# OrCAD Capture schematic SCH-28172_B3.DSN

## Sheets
1 TABLE OF CONTENT/REVISIONS: title: FRDM-KL03Z; rev: B3; company: Freescale Semiconductor; note: SCH-28172 PDF:SPF-28172; note: 6501 William Cannon Drive West; note: Austin, TX 78735-8598
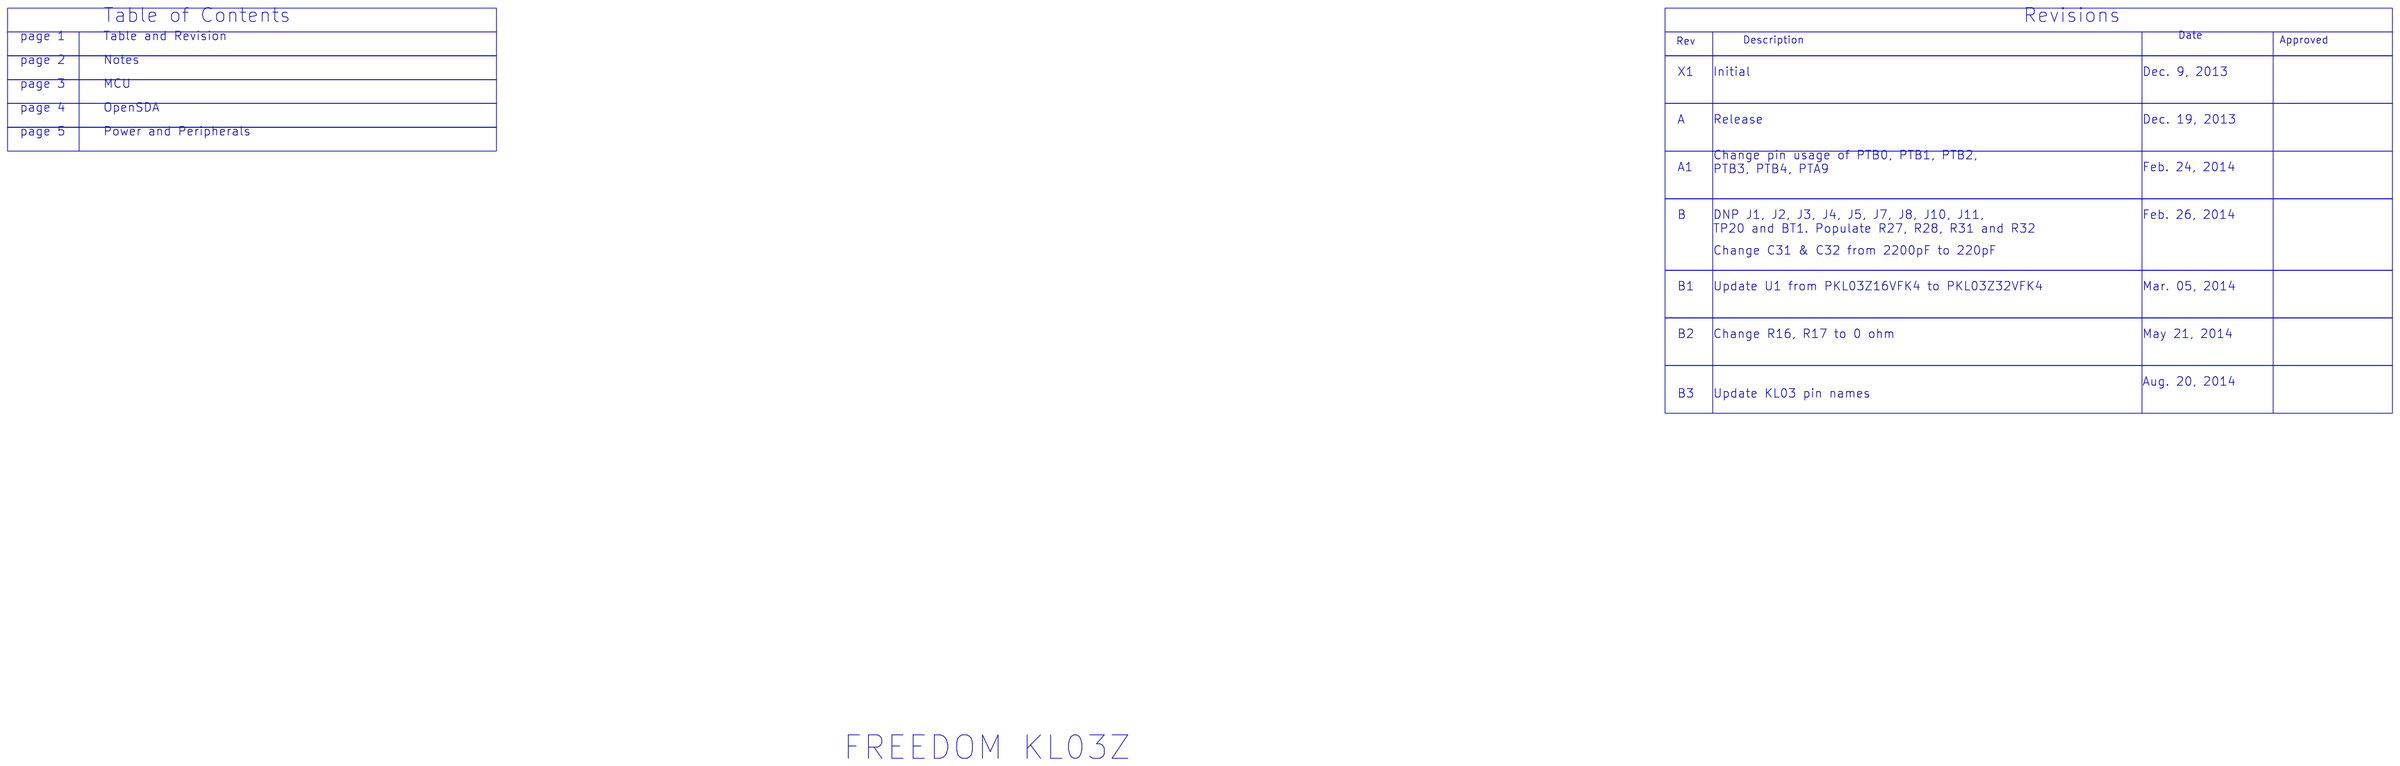
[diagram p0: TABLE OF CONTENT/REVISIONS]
2 NOTES
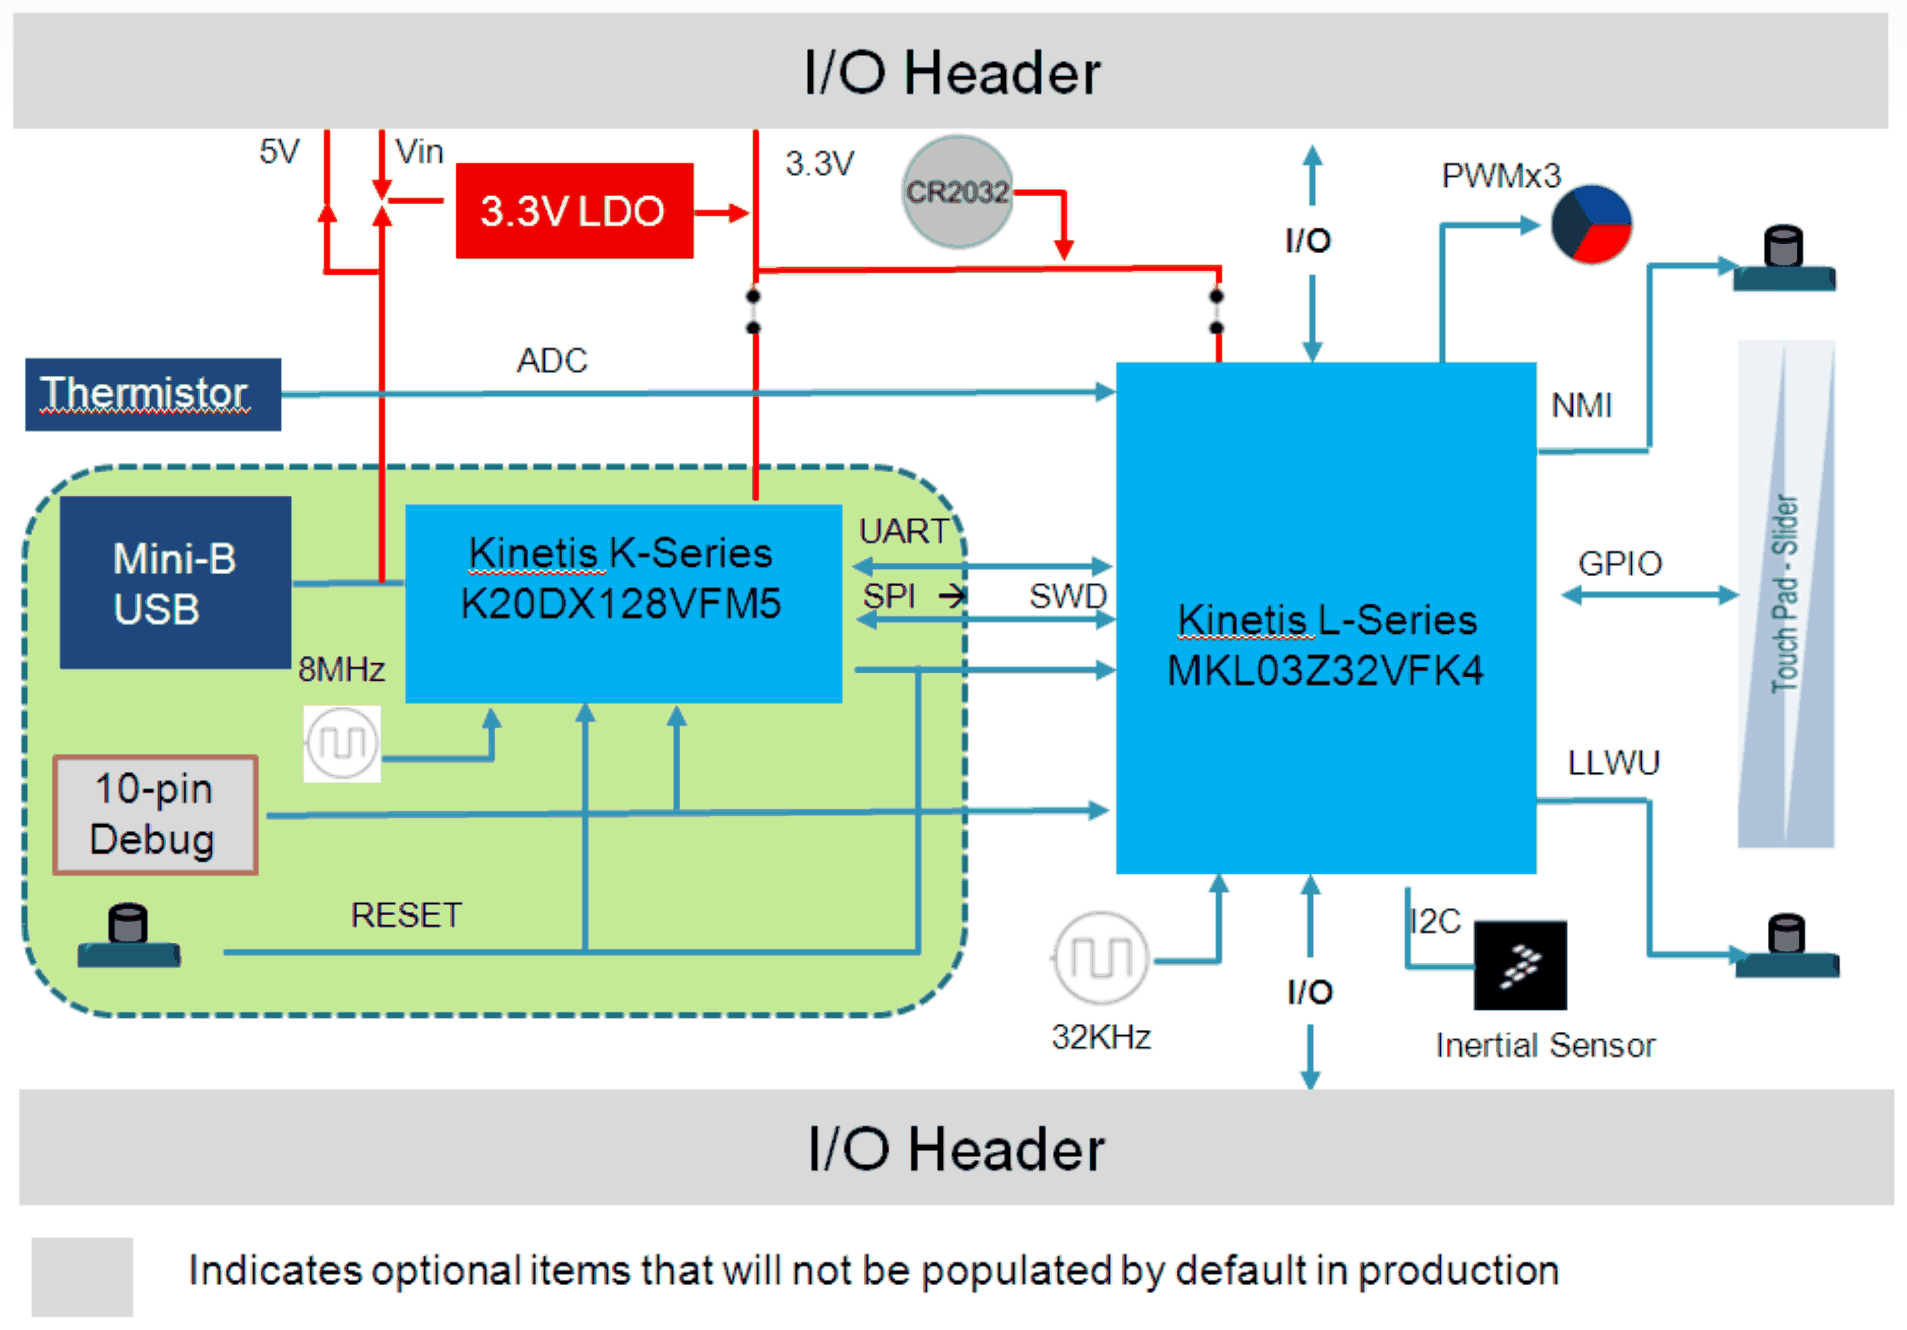
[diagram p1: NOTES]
3 MCU: size C
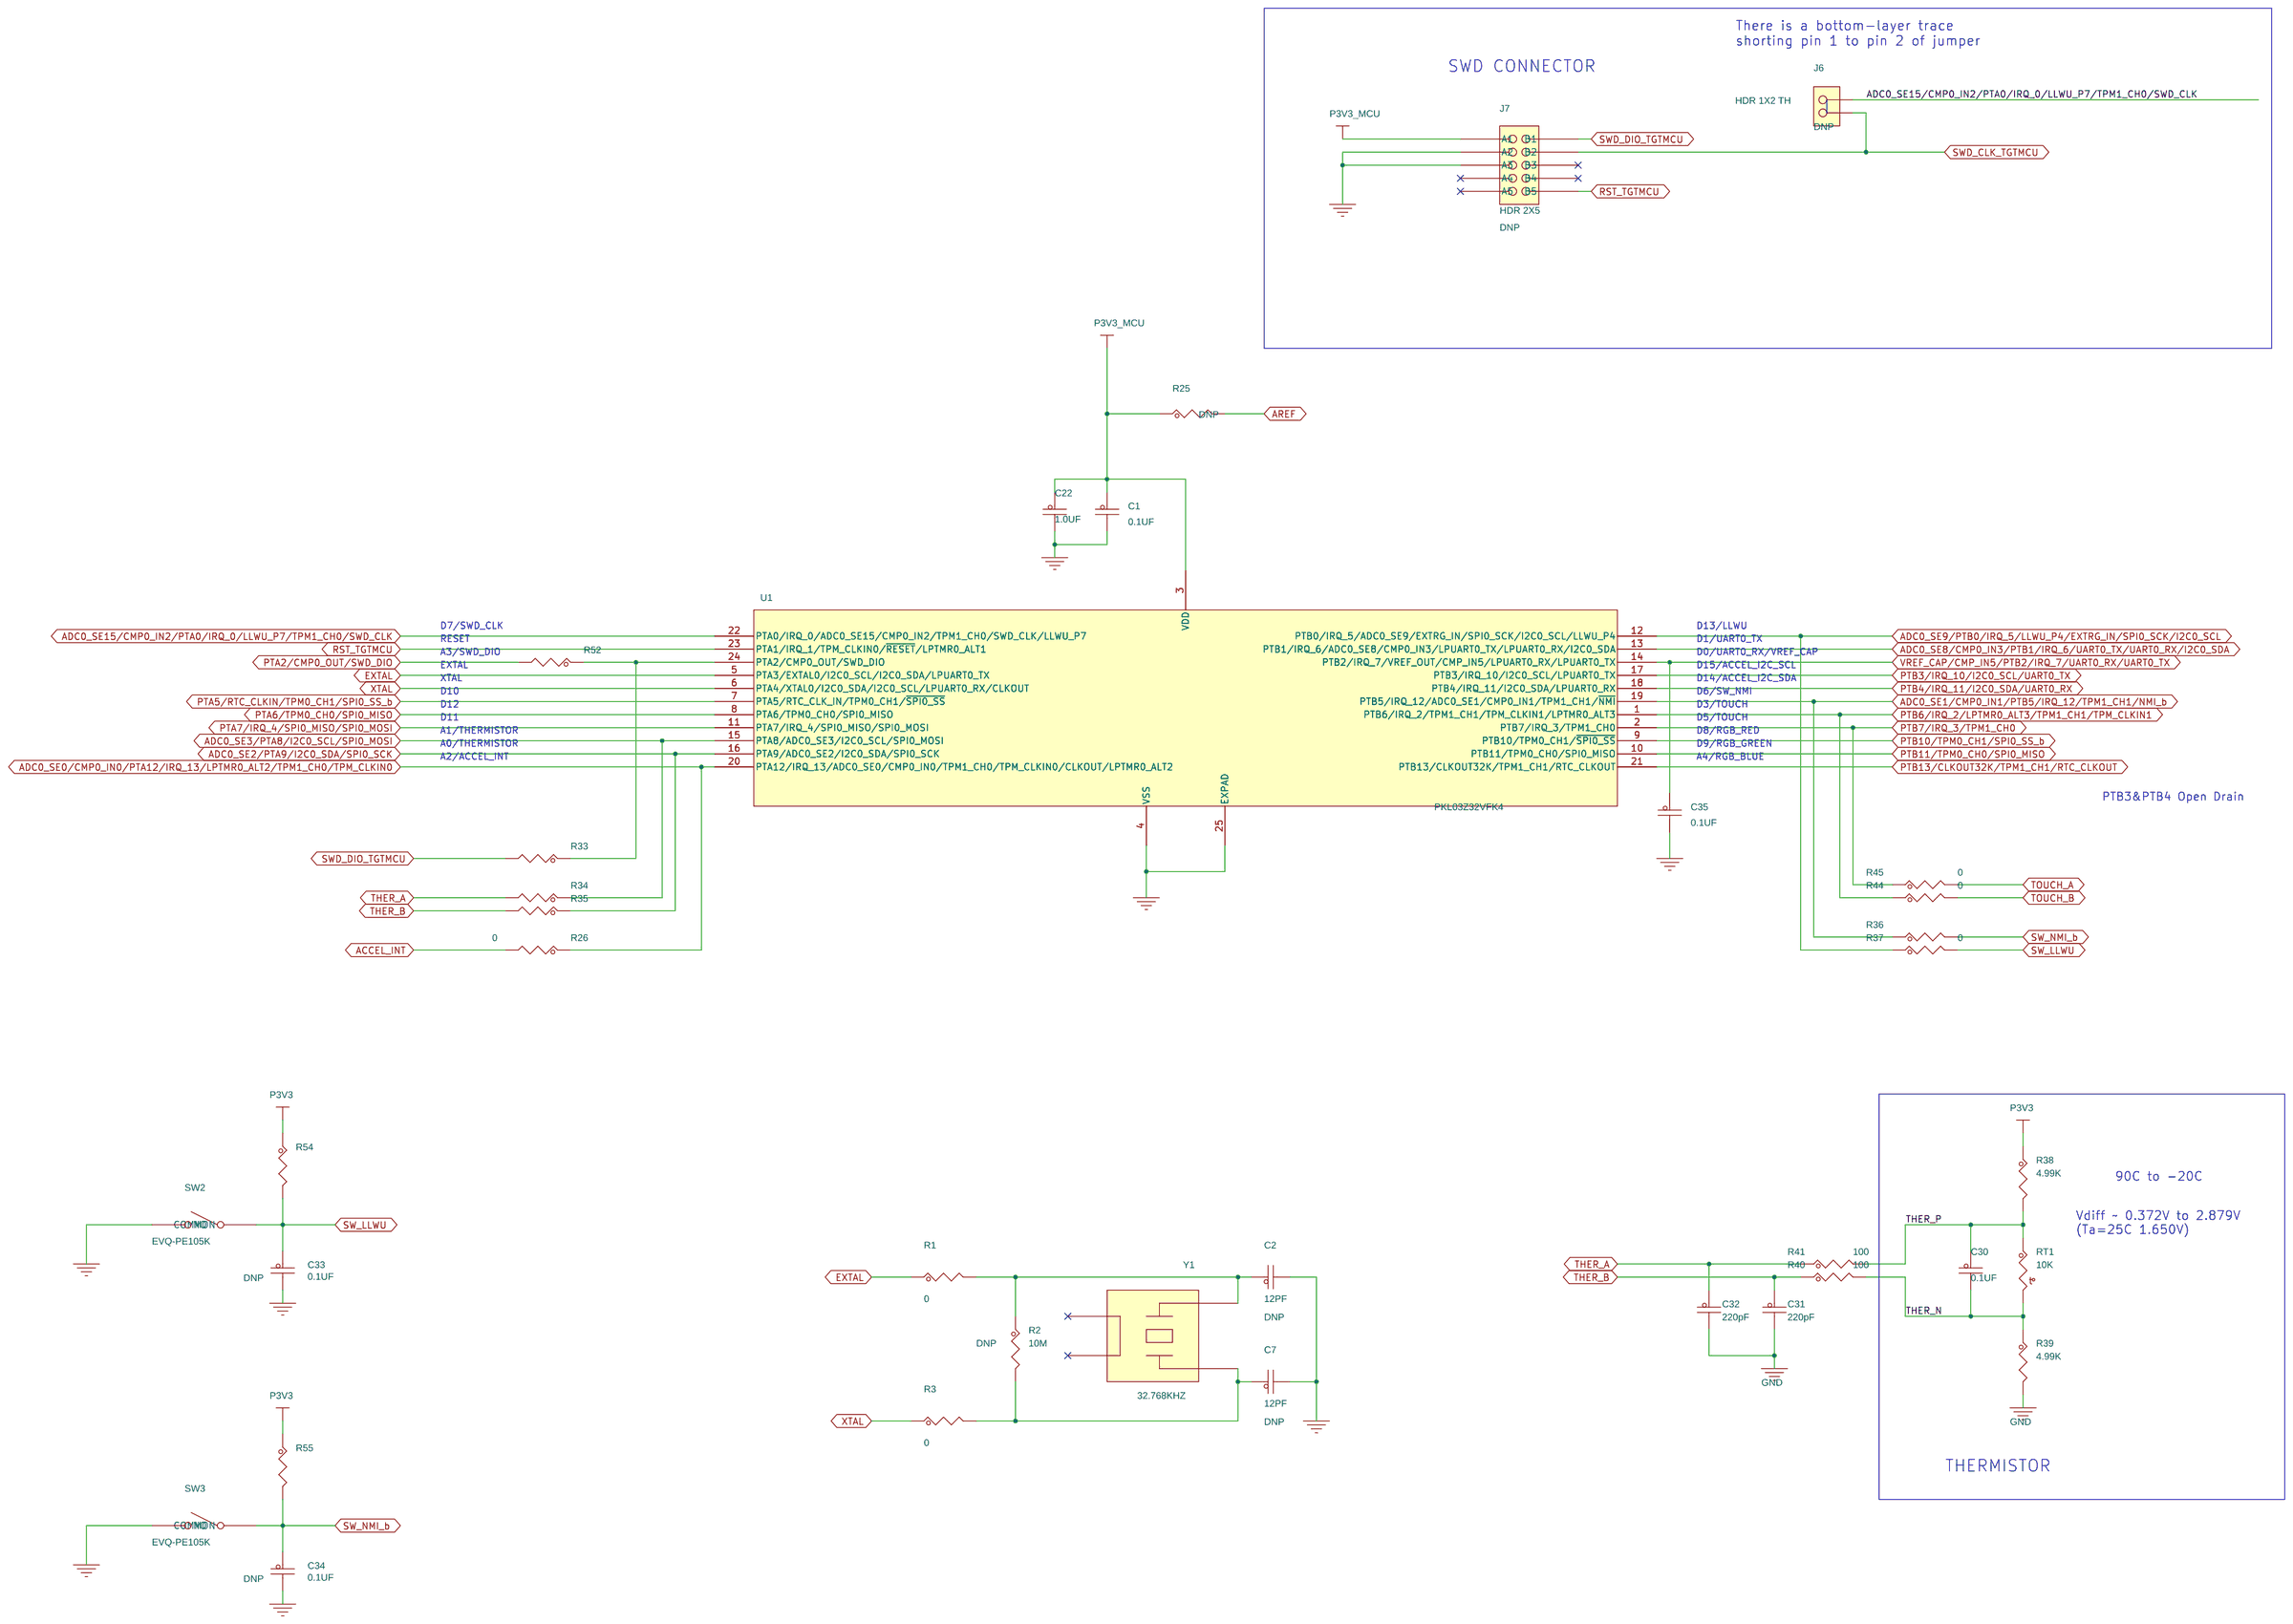
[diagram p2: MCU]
4 OPEN-SDA interface: size C
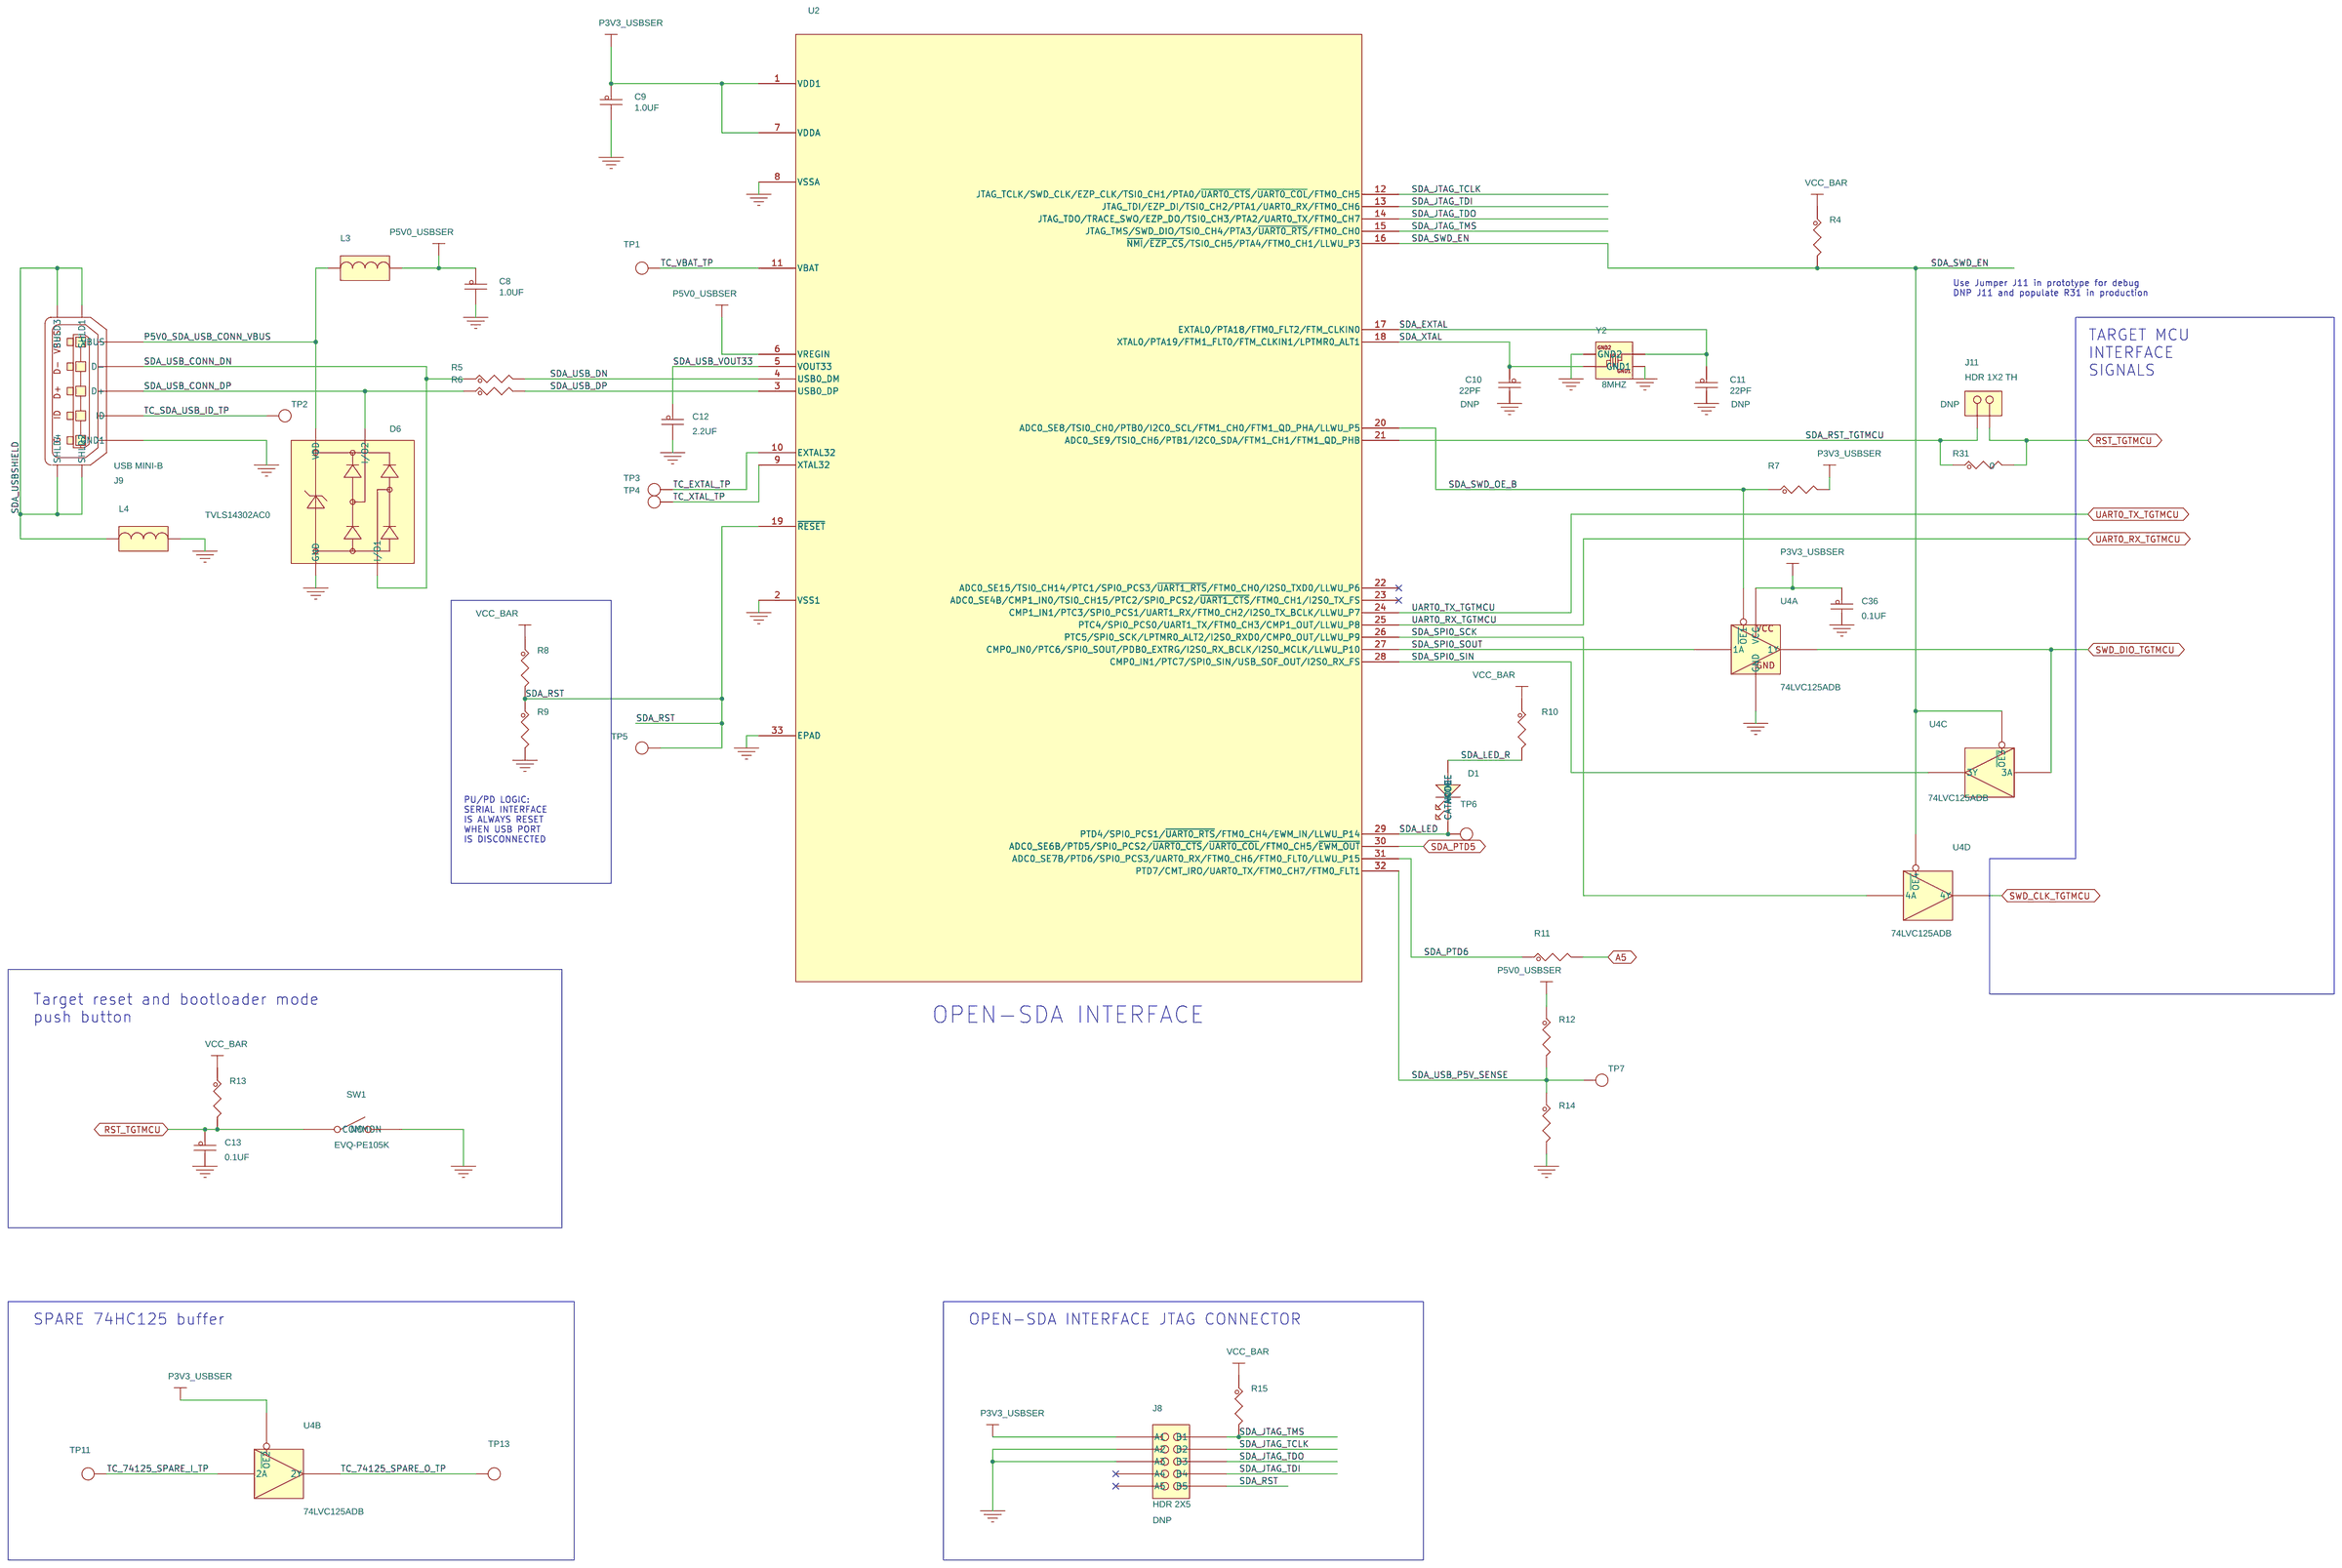
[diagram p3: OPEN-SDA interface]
5 PWR & PERIPHERALS: size C
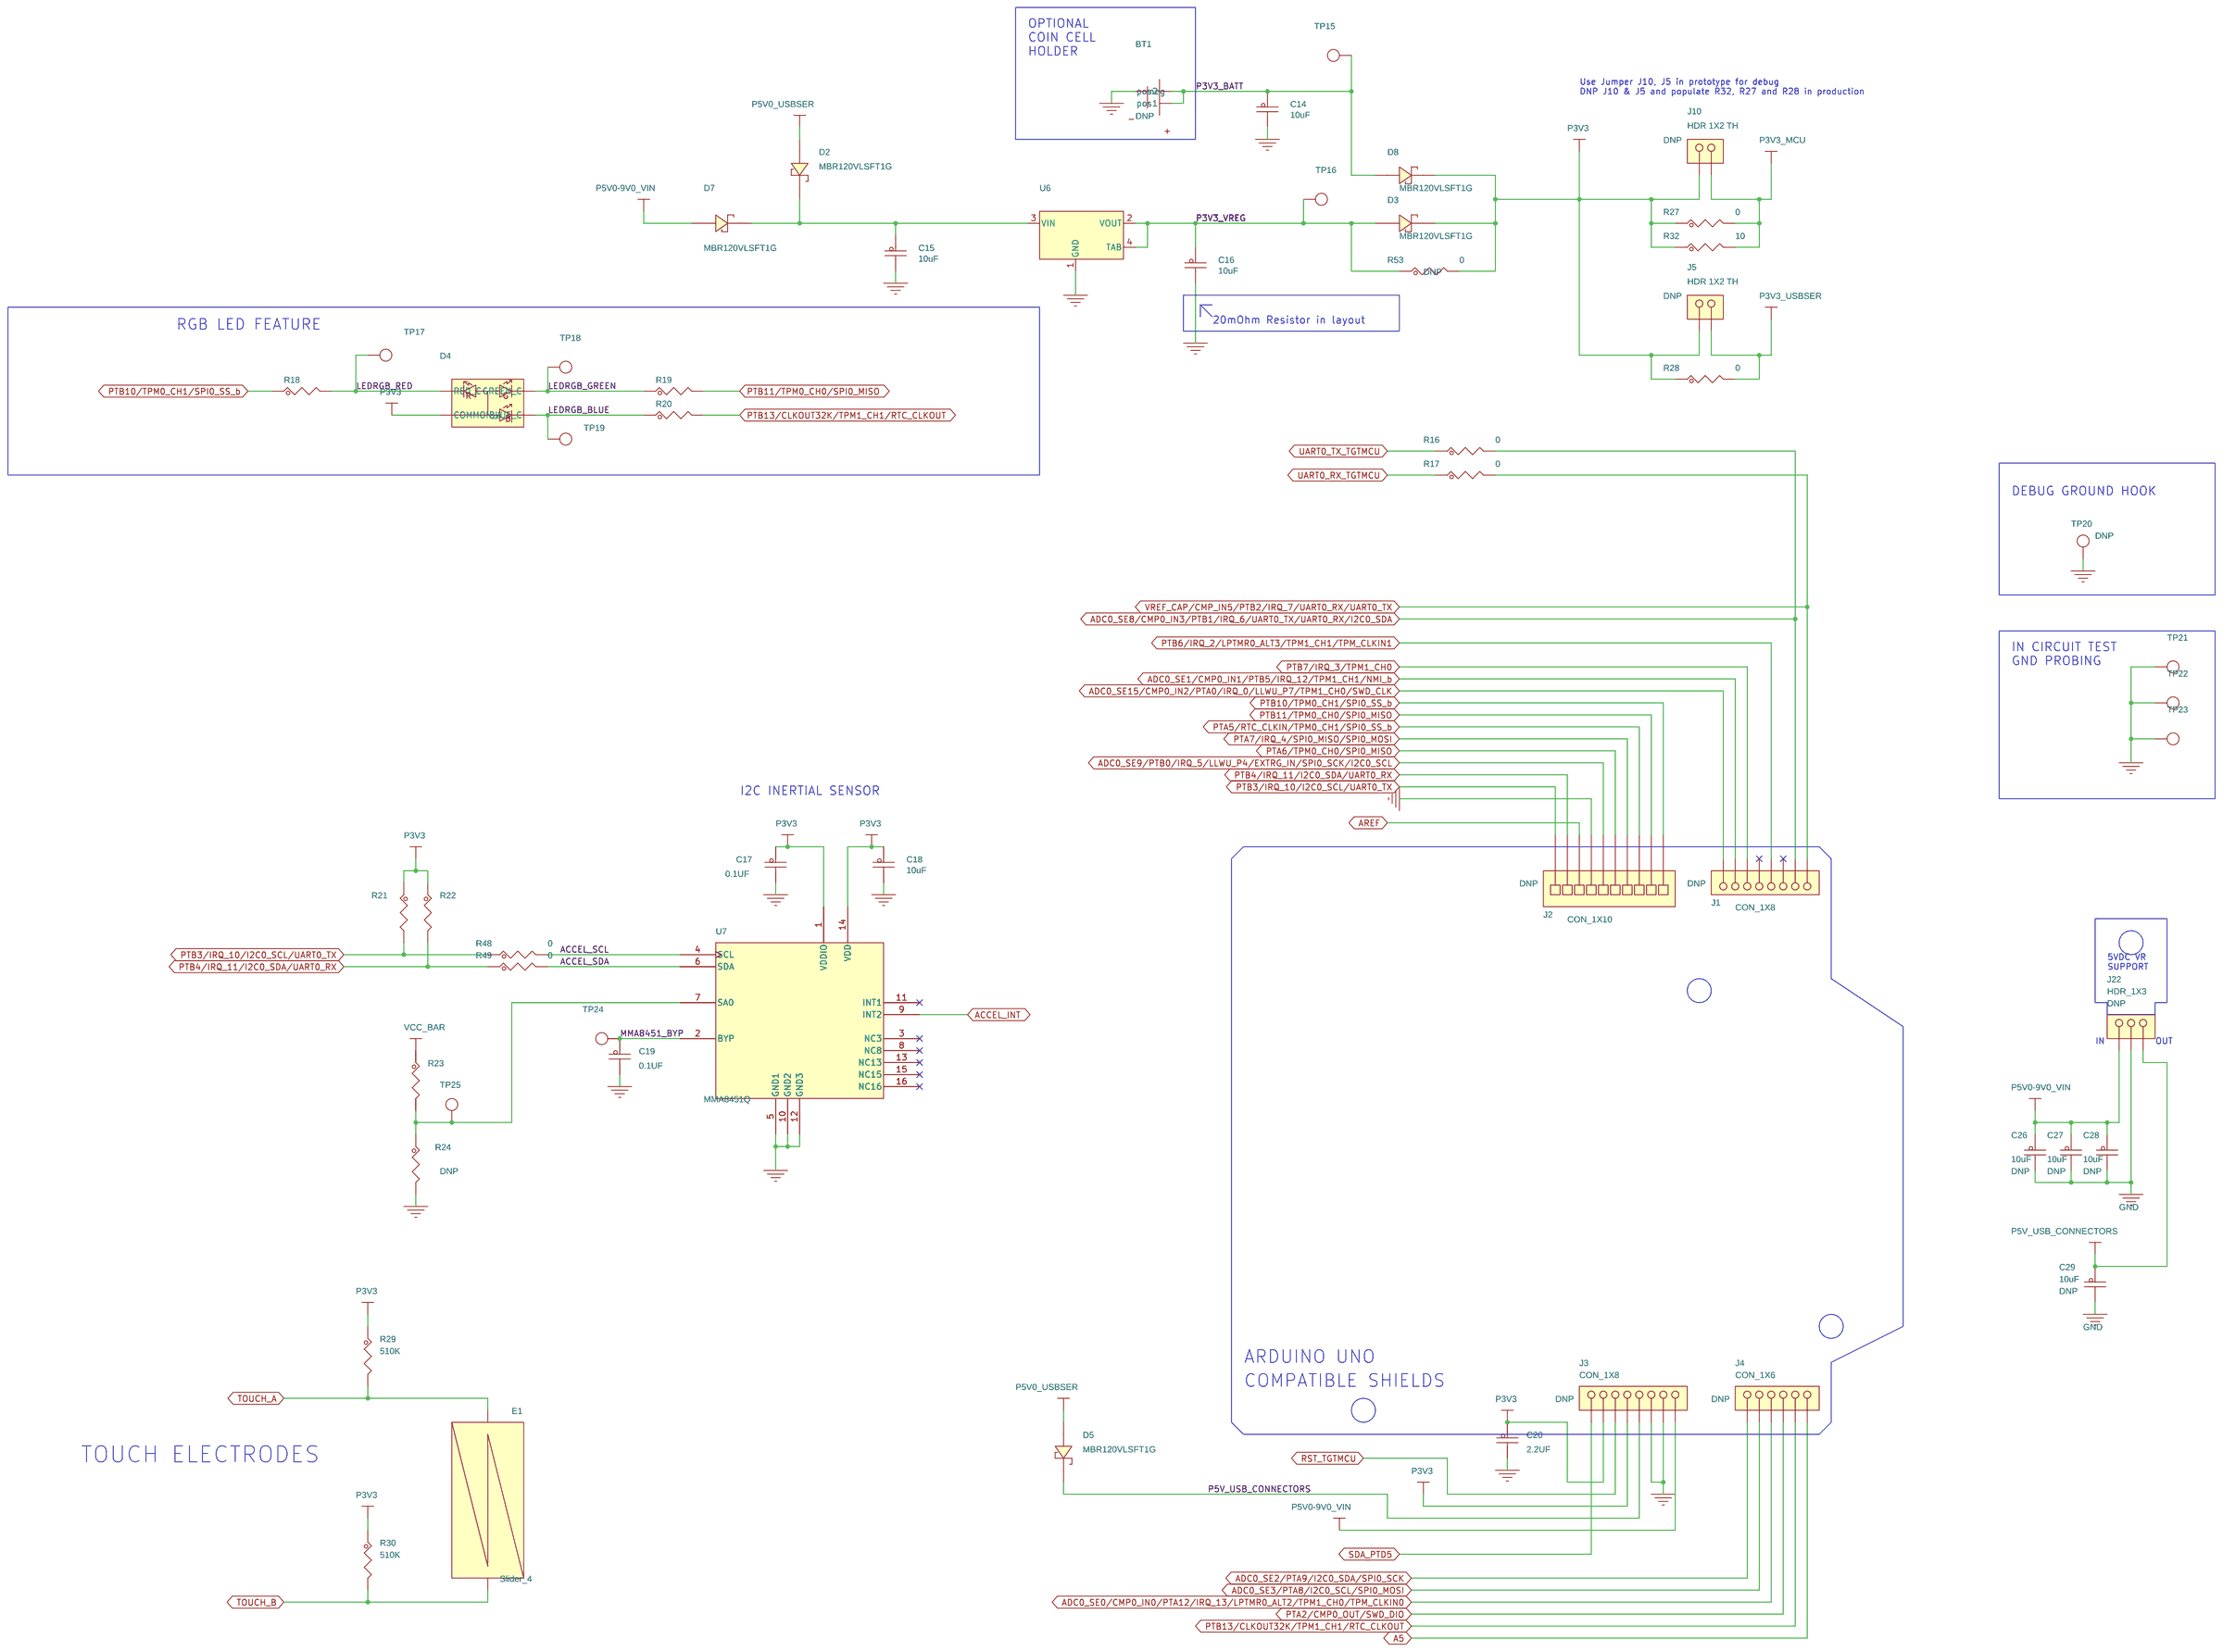
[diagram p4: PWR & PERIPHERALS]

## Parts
sheet MCU
C1  0.1UF  [CC0402_25]
C2  12PF  [CC0402_25]
C7  12PF  [CC0402_25]
C22  1.0UF  [CC0402_25]
C30  0.1UF  [CC0402_25]
C31  220pF  [CC0402_25]
C32  220pF  [CC0402_25]
C33  0.1UF  [CC0402_25]
C34  0.1UF  [CC0402_25]
C35  0.1UF  [CC0402_25]
J6  HDR 1X2 TH  [SH_HDR102_BOTTOM]
J7  HDR 2X5  [hdr_5X2_ftsh_th_nsp]
R1  0  [RC0603_OV]
R2  10M  [RC0603_OV]
R3  0  [RC0603_OV]
R25  0  [RC0603_OV]
R26  0  [RC0603_OV]
R33  0  [RC0603_OV]
R34  0  [RC0603_OV]
R35  0  [RC0603_OV]
R36  0  [RC0603_OV]
R37  0  [RC0603_OV]
R38  4.99K  [RC0603_OV]
R39  4.99K  [RC0603_OV]
R40  100  [RC0402_25]
R41  100  [RC0402_25]
R44  0  [RC0603_OV]
R45  0  [RC0603_OV]
R52  0  [RC0603_OV]
R54  10K  [RC0603_OV]
R55  10K  [RC0603_OV]
RT1  10K  [RC0603_OV]
SW2  EVQ-PE105K  [sw2_spst_3p5x6p0_5p0]
SW3  EVQ-PE105K  [sw2_spst_3p5x6p0_5p0]
U1  PKL03Z32VFK4  [QFN24_0P5_4X4MM]
Y1  32.768KHZ  [xtlosc4_8x4mm]
sheet OPEN-SDA interface
C8  1.0UF  [CC0402_25]
C9  1.0UF  [CC0402_25]
C10  22PF  [CC0402_25]
C11  22PF  [CC0402_25]
C12  2.2UF  [CC0603_OV]
C13  0.1UF  [CC0402_25]
C36  0.1UF  [CC0402_25]
D1  LED GREEN  [LED_0603]
D6  TVLS14302AC0  [sot_143]
J8  HDR 2X5  [hdr_5X2_ftsh_th_nsp]
J9  USB MINI-B  [con5_usb_b_ubb]
J11  HDR 1X2 TH  [HDR102]
L3  330 OHM  [IND_0805]
L4  330 OHM  [IND_0805]
R4  10K  [RC0603_OV]
R5  33  [RC0402_25]
R6  33  [RC0402_25]
R7  10K  [RC0603_OV]
R8  4.7K  [RC0603_OV]
R9  10K  [RC0603_OV]
R10  220  [RC0603_OV]
R11  0  [RC0603_OV]
R12  4.7K  [RC0603_OV]
R13  10K  [RC0603_OV]
R14  10K  [RC0603_OV]
R15  10K  [RC0603_OV]
R31  0  [RC0603_OV]
SW1  EVQ-PE105K  [sw2_spst_3p5x6p0_5p0]
TP1  TP_PTH  [TP_PTH]
TP2  TP_PTH  [TP_PTH]
TP3  TP_PTH  [TP_PTH]
TP4  TP_PTH  [TP_PTH]
TP5  TPAD_030  [TPAD_030]
TP6  TPAD_030  [TPAD_030]
TP7  TPAD_030  [TPAD_030]
TP11  TP_PTH  [TP_PTH]
TP13  TP_PTH  [TP_PTH]
U2  MK20DX128VFM5  [QFN32_S142EP]
U4  74LVC125ADB  [ssop14]  (sections A,B,C,D)
Y2  8MHZ  [xtlosc4_5x3MM_sm]
sheet PWR & PERIPHERALS
BT1  3003  [batt_21x20mm]
C14  10uF  [CC0603_OV]
C15  10uF  [CC0603_OV]
C16  10uF  [CC0603_OV]
C17  0.1UF  [CC0402_25]
C18  10uF  [CC0603_OV]
C19  0.1UF  [CC0402_25]
C20  2.2UF  [CC0603_OV]
C26  10uF  [CC0603_OV]
C27  10uF  [CC0603_OV]
C28  10uF  [CC0603_OV]
C29  10uF  [CC0603_OV]
D2  MBR120VLSFT1G  [SOD-123]
D3  MBR120VLSFT1G  [SOD-123]
D4  CLV1A-FKB-CJ1M1F1BB7R4S3  [led4_3p4x3mm_smt]
D5  MBR120VLSFT1G  [SOD-123]
D7  MBR120VLSFT1G  [SOD-123]
D8  MBR120VLSFT1G  [SOD-123]
E1  Slider_4  [electrode_tri_4_12x38mm]
J1  CON_1X8  [con_1x8_skt_2p54_th]
J2  CON_1X10  [HDR110]
J3  CON_1X8  [con_1x8_skt_2p54_th]
J4  CON_1X6  [con_skt1x6_th]
J5  HDR 1X2 TH  [HDR102]
J10  HDR 1X2 TH  [HDR102]
J22  HDR_1X3  [HDR103]
R16  0  [RC0603_OV]
R17  0  [RC0603_OV]
R18  220  [RC0603_OV]
R19  220  [RC0603_OV]
R20  220  [RC0603_OV]
R21  4.7K  [RC0603_OV]
R22  4.7K  [RC0603_OV]
R23  10K  [RC0603_OV]
R24  10K  [RC0603_OV]
R27  0  [RC0603_OV]
R28  0  [RC0603_OV]
R29  510K  [RC0603_OV]
R30  510K  [RC0603_OV]
R32  10  [RC0603_OV]
R48  0  [RC0603_OV]
R49  0  [RC0603_OV]
R53  0  [RC0603_OV]
TP15  TPAD_030  [TPAD_030]
TP16  TPAD_030  [TPAD_030]
TP17  TPAD_030  [TPAD_030]
TP18  TPAD_030  [TPAD_030]
TP19  TPAD_030  [TPAD_030]
TP20  TEST POINT WHITE  [TEST_LOOP]
TP21  TPAD_030  [TPAD_030]
TP22  TPAD_030  [TPAD_030]
TP23  TPAD_030  [TPAD_030]
TP24  TPAD_030  [TPAD_030]
TP25  TPAD_030  [TPAD_030]
U6  NCP1117ST33T3G  [sot223]
U7  MMA8451Q  [QFN5X3_0P5_3X3]

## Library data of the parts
C1 C13 C17 C19 C30 C35 C36 = CAP_NP: CAP CER 0.1UF 10V 10% X5R 0402; AGILE_PN: 150-75634; CAD_APPROVED: Yes; FPLIST: CC0402_25,CC0402_HD,0402_CC; HEIGHT: 0.64MM; MFG_NAME01: KEMET; MFG_PN01: C0402C104K8PAC; ROHS: Yes; Tolerance: 10%; VOLTAGE: 10V
C2 C7 = CAP_NP: CAP CER 12PF 50V 5% C0G 0402; AGILE_PN: 150-75680; ASSY_OPT: DNP; CAD_APPROVED: Yes; FPLIST: CC0402_25,CC0402_HD,0402_CC; HEIGHT: 0.55MM; MFG_NAME01: MURATA; MFG_PN01: GRM1555C1H120JZ01D; ROHS: Yes; Tolerance: 5%; VOLTAGE: 50V
C8 C9 C22 = CAP_NP: CAP CER 1.0UF 10V 10% X5R 0402; AGILE_PN: 150-75772; CAD_APPROVED: Yes; FPLIST: CC0402_25,CC0402_HD,0402_CC; HEIGHT: 0.6MM; MFG_NAME01: YAGEO AMERICA; MFG_PN01: CC0402KRX5R6BB105; ROHS: Yes; VOLTAGE: 10V
C31 C32 = CAP_NP: CAP CER 220PF 50V 10% X7R 0402; AGILE_PN: 150-75829; CAD_APPROVED: Yes; FPLIST: CC0402_25,CC0402_HD,0402_CC; HEIGHT: 0.55MM; MFG_NAME01: MURATA; MFG_PN01: GRM155R71H221KA01J; ROHS: Yes; Tolerance: 10%; VOLTAGE: 50V
C33 C34 = CAP_NP: CAP CER 0.1UF 10V 10% X5R 0402; AGILE_PN: 150-75634; ASSY_OPT: DNP; CAD_APPROVED: Yes; FPLIST: CC0402_25,CC0402_HD,0402_CC; HEIGHT: 0.64MM; MFG_NAME01: KEMET; MFG_PN01: C0402C104K8PAC; ROHS: Yes; Tolerance: 10%; VOLTAGE: 10V
J5 J6 J10 J11 = CONN_HDR_2X1: HDR 1X2 TH 100MIL SP 339H AU 98L; AGILE_PN: 210-75439; ASSY_OPT: DNP; CAD_APPROVED: YES; FPLIST: HDR102,SH_HDR102_BOTTOM; HEIGHT: 8.71 MM; MFG_NAME01: SAMTEC; MFG_PN01: TSW-102-07-G-S; ROHS: Yes
J7 J8 = CONN_HDR_5X2: HDR 2X5 TH 50MIL CTR 167H AU 91L; AGILE_PN: 210-80192; ASSY_OPT: DNP; CAD_APPROVED: Yes; FPLIST: hdr_5X2_ftsh_th,hdr_5X2_ftsh_th_nsp; HEIGHT: 4.25MM; MFG_NAME01: ANYTRONIC CORPORATION LIMITED; MFG_PN01: 0922S0205011N6T-2LF; ROHS: Yes
R1 R3 R11 R16 R17 R26-R28 R31 R33-R37 R44 R45 R48 R49 R52 = RES: RES MF ZERO OHM 1/10W -- 0603; AGILE_PN: 470-75407; CAD_APPROVED: Yes; FPLIST: RC0603_OV,RC0603,R603-X2,0603_CC; MFG_NAME01: VISHAY INTERTECHNOLOGY; MFG_PN01: CRCW06030000Z0EA; ROHS: Yes; Tolerance: 1%
R2 = RES: RES MF 10M 1/10W 1% 0603; AGILE_PN: 470-30139; ASSY_OPT: DNP; CAD_APPROVED: Yes; FPLIST: RC0603_OV,RC0603,0603_CC; MFG_NAME01: KOA SPEER; MFG_PN01: RK73H1JTTD1005F; ROHS: Yes; Tolerance: 1%
R25 R53 = RES: RES MF ZERO OHM 1/10W -- 0603; AGILE_PN: 470-75407; ASSY_OPT: DNP; CAD_APPROVED: Yes; FPLIST: RC0603_OV,RC0603,R603-X2,0603_CC; MFG_NAME01: VISHAY INTERTECHNOLOGY; MFG_PN01: CRCW06030000Z0EA; ROHS: Yes; Tolerance: 1%
R38 R39 = RES: RES MF 4.99K 1/10W 1% 0603; AGILE_PN: 470-75771; CAD_APPROVED: Yes; FPLIST: RC0603_OV,RC0603,0603_CC; MFG_NAME01: KOA SPEER; MFG_PN01: RK73H1JTTD4991F; ROHS: Yes; Tolerance: 1%
R40 R41 = RES: RES MF 100 OHM 1/16W 1% 0402; AGILE_PN: 470-30454; CAD_APPROVED: Yes; FPLIST: RC0402_25,RC0402_HD,0402_CC; MFG_NAME01: THYE MING TECH CO LTD; MFG_PN01: CR-02FL6--100R; ROHS: Yes; Tolerance: 1%
R4 R7 R9 R13-R15 R23 R54 R55 = RES: RES MF 10K 1/10W 5% 0603; AGILE_PN: 470-75410; CAD_APPROVED: Yes; FPLIST: RC0603_OV,RC0603,0603_CC; MFG_NAME01: KOA SPEER; MFG_PN01: RK73B1JTTD103J; ROHS: Yes; Tolerance: 5%
RT1 = THERMISTOR: THERMISTOR 10K 1/10W 1% 0603; AGILE_PN: 470-80022; CAD_APPROVED: Yes; FPLIST: RC0603_OV,RC0603,0603_CC; MFG_NAME01: MuRata; MFG_PN01: NCP18XH103F03RB; ROHS: Yes; Tolerance: 1%
SW1-SW3 = SW2P: SW SPST NO 0.05A 12V SMD; AGILE_PN: 510-77858; CAD_APPROVED: Yes; HEIGHT: 5.2 MM; MFG_NAME01: PANASONIC; MFG_PN01: EVQPE105K; ROHS: Yes
U1 = PKL03Z32_QFN_25P: IC MCU 32KB FLASH 48MHz 1.71-3.6V QFN24; AGILE_PN: 344-01990; CAD_APPROVED: Yes; HEIGHT: 0.65MM; MFG_NAME01: FREESCALE SEMICONDUCTOR; ROHS: Yes
Y1 = CRYSTAL1-4_SM: XTAL 32.768KHZ FIXED PAR -- SMT 8X4MM; AGILE_PN: 230-76552; CAD_APPROVED: Yes; HEIGHT: 2.5MM; MFG_NAME01: ABRACON CORP; MFG_PN01: ABS25-32.768KHZ-T; ROHS: Yes
C10 C11 = CAP_NP: CAP CER 22PF 50V 5% C0G 0402; AGILE_PN: 150-75266; ASSY_OPT: DNP; CAD_APPROVED: Yes; FPLIST: CC0402_25,CC0402_HD,0402_CC; HEIGHT: 0.635MM; MFG_NAME01: AVX; MFG_PN01: 04025A220JAT2A; ROHS: Yes; Tolerance: 5%; VOLTAGE: 50V
C12 C20 = CAP_NP: CAP CER 2.2UF 10V 10% X7R 0603; AGILE_PN: 150-78564; CAD_APPROVED: Yes; FPLIST: CC0603_OV,CC0603,0603_CC; HEIGHT: 1.25MM; MFG_NAME01: TAIYO YUDEN; MFG_PN01: LMK107B7225KA-T; ROHS: Yes; Tolerance: 10%; VOLTAGE: 10V
D1 = LED: LED GRN SGL 20MA 0603; AGILE_PN: 370-76565; CAD_APPROVED: Yes; HEIGHT: 0.67MM; MFG_NAME01: osram; MFG_PN01: LG L29K-G2J1-24-Z; ROHS: Yes
D6 = DIODE_TVS_SOT143: DIODE TVS ARRAY 8KV 6V SOT143; AGILE_PN: 480-78339; CAD_APPROVED: Yes; HEIGHT: 1.15 MM; MFG_NAME01: INPAQ TECHNOLOGY (SUZHOU) CO., LTD; ROHS: Yes
J9 = USB_MINI_B_SKT: CON 1X5 USB MINI-B RA SHLD SKT SMT 0.8MM SP 162H --; AGILE_PN: 211-79256; CAD_APPROVED: Yes; HEIGHT: 4.1 MM; MFG_NAME01: KALER ELECTRONICS CO., LTD; MFG_PN01: UBB05V102-B0C04B; ROHS: Yes
L3 L4 = BEAD: IND FER BEAD 330OHM@100MHZ 2.5A -- SMT; AGILE_PN: 180-30021; CAD_APPROVED: YES; HEIGHT: 1.05 MM; MFG_NAME01: TDK; MFG_PN01: MPZ2012S331A; PART_TYPE: FERRITE; ROHS: Yes; Tolerance: 25%
R5 R6 = RES: RES MF 33.0 OHM 1/16W 1% 0402; AGILE_PN: 470-75790; CAD_APPROVED: Yes; FPLIST: RC0402_25,RC0402_HD,RC0402_X2,0402_CC; MFG_NAME01: THYE MING TECH CO LTD; MFG_PN01: CR-02FL6---33R; ROHS: Yes; Tolerance: 1%
R8 R12 R21 R22 = RES: RES MF 4.7K 1/10W 5% 0603; AGILE_PN: 470-75414; CAD_APPROVED: Yes; FPLIST: RC0603_OV,RC0603,0603_CC; MFG_NAME01: VISHAY INTERTECHNOLOGY; MFG_PN01: CRCW06034K70JNEA; ROHS: Yes; Tolerance: 5%
R10 R18-R20 = RES: RES MF 220 OHM 1/10W 5% 0603; AGILE_PN: 470-30297; CAD_APPROVED: Yes; FPLIST: RC0603_OV,RC0603,0603_CC; MFG_NAME01: KOA SPEER; MFG_PN01: RK73B1JTTD221J; ROHS: Yes; Tolerance: 5%
TP1-TP4 TP11 TP13 = TESTLOOP: TEST POINT PAD 035-018MIL TH, NO PART TO ORDER; AGILE_PN: 210-77612; CAD_APPROVED: Yes; HEIGHT: 0.1 mm; MFG_NAME01: NOTACOMPONENT; MFG_PN01: NOTACOMPONENT; ROHS: Yes
TP5-TP7 TP15-TP19 TP21-TP25 = TESTLOOP: TEST POINT PAD 30MIL DIA SMT, NO PART TO ORDER; AGILE_PN: 211-76642; CAD_APPROVED: Yes; HEIGHT: 0.1MM; MFG_NAME01: NOTACOMPONENT; MFG_PN01: NOTACOMPONENT; ROHS: Yes
U2 = PK20DX128V_QFN_32P: IC MCU FLASH 128KB 50MHZ 1.71-3.6V QFN32; AGILE_PN: 344-01231; CAD_APPROVED: Yes; HEIGHT: 1MM; MFG_NAME01: FREESCALE SEMICONDUCTOR; ROHS: Yes
U4 = 74-125_14P: IC BUF QUAD TS 1.2-3.6V SSOP14; AGILE_PN: 312-79933; CAD_APPROVED: Yes; HEIGHT: 2mm; MFG_NAME01: NXP SEMICONDUCTORS; ROHS: Yes
Y2 = CRYSTAL_JXS63: XTAL 8MHZ 20PPM PAR 18PF ESR 200OHM SMT; AGILE_PN: 230-77754; CAD_APPROVED: Yes; HEIGHT: 1.1MM; MFG_NAME01: Abracon Corporation; MFG_PN01: ABM3B-8.000MHZ-B2-T; ROHS: Yes
BT1 = BATTERY_SKT_3V: HOLDER BATTERY 20MM DIA TH; AGILE_PN: 801-76130; ASSY_OPT: DNP; CAD_APPROVED: Yes; HEIGHT: 4.21MM; MFG_NAME01: Keystone Electronics; ROHS: Yes
C14-C16 C18 = CAP_NP: CAP CER 10UF 10V 20% X5R 0603; AGILE_PN: 150-78609; CAD_APPROVED: Yes; FPLIST: CC0603_OV,CC0603,0603_CC; HEIGHT: 1.016MM; MFG_NAME01: TAIYO YUDEN; MFG_PN01: LMK107BJ106MALTD; ROHS: Yes; VOLTAGE: 10V
C26-C29 = CAP_NP: CAP CER 10UF 10V 20% X5R 0603; AGILE_PN: 150-78609; ASSY_OPT: DNP; CAD_APPROVED: Yes; FPLIST: CC0603_OV,CC0603,0603_CC; HEIGHT: 1.016MM; MFG_NAME01: TAIYO YUDEN; MFG_PN01: LMK107BJ106MALTD; ROHS: Yes; VOLTAGE: 10V
D2 D3 D5 D7 D8 = DIODE_SCHTKY: DIODE SCH RECT 1A 20V SMT; AGILE_PN: 480-75997; CAD_APPROVED: Yes; HEIGHT: 1MM; MFG_NAME01: ON SEMICONDUCTOR; ROHS: Yes
D4 = CLV1A_LED_4P: LED RED BL GRN SGL 50/25/25mA SMT; AGILE_PN: 370-76567; CAD_APPROVED: Yes; HEIGHT: 2.1MM; MFG_NAME01: CREE, INC; ROHS: Yes
E1 = ELECTRODE_TRI_2: ELECTRODE SLIDER 4 TRIANGLE, NO PART TO ORDER; AGILE_PN: 510-77835; CAD_APPROVED: Yes; HEIGHT: 0.127MM; MFG_NAME01: NO PART TO ORDER; MFG_PN01: NO PART TO ORDER; ROHS: Yes
J1 J3 = CONN_HDR_8X1: CON 1X8 SKT TH 100MIL SP 335H AU 104L; AGILE_PN: 210-79539; ASSY_OPT: DNP; CAD_APPROVED: Yes; HEIGHT: 8.51MM; MFG_NAME01: SAMTEC; MFG_PN01: SSW-108-01-G-S; ROHS: Yes
J2 = RCPT_1X10: CON 1X10 SKT TH 100MIL SP 335H AU; AGILE_PN: 210-75438; ASSY_OPT: DNP; CAD_APPROVED: Yes; HEIGHT: 8.51 MM; MFG_NAME01: SAMTEC; MFG_PN01: SSW-110-01-G-S; ROHS: Yes
J4 = CONN_HDR_6X1: CON 1X6 SKT TH 100MIL SP 335H AU 104L; AGILE_PN: 210-79530; ASSY_OPT: DNP; CAD_APPROVED: Yes; HEIGHT: 8.76MM; MFG_NAME01: SAMTEC; MFG_PN01: SSW-106-01-G-S; ROHS: Yes
J22 = CONN_HDR_3X1: HDR 1X3 TH 100MIL SP 330H AU 98L; AGILE_PN: 210-75442; ASSY_OPT: DNP; CAD_APPROVED: Yes; HEIGHT: 8.38 MM; MFG_NAME01: SAMTEC; MFG_PN01: HTSW-103-07-S-S; ROHS: Yes
R24 = RES: RES MF 10K 1/10W 5% 0603; AGILE_PN: 470-75410; ASSY_OPT: DNP; CAD_APPROVED: Yes; FPLIST: RC0603_OV,RC0603,0603_CC; MFG_NAME01: KOA SPEER; MFG_PN01: RK73B1JTTD103J; ROHS: Yes; Tolerance: 5%
R29 R30 = RES: RES MF 510K 1/10W 5% 0603; AGILE_PN: 470-80477; CAD_APPROVED: Yes; FPLIST: RC0603_OV,RC0603,0603_CC; MFG_NAME01: YAGEO AMERICA; MFG_PN01: RC0603JR-07510KL; ROHS: Yes; Tolerance: 5%
R32 = RES: RES MF 10.0 OHM 1/10W 1% 0603; AGILE_PN: 470-75423; CAD_APPROVED: Yes; FPLIST: RC0603_OV,RC0603,0603_CC; MFG_NAME01: KOA SPEER; MFG_PN01: RK73H1JTTD10R0F; ROHS: Yes; Tolerance: 1%
TP20 = TESTLOOP: TEST POINT WHITE 40 MIL DRILL 180 MIL TH 109L; AGILE_PN: 210-75685; ASSY_OPT: DNP; CAD_APPROVED: Yes; HEIGHT: 4.8 MM; MFG_NAME01: KEYSTONE ELECTRONICS; MFG_PN01: 5002; ROHS: Yes
U6 = LD1117AS18: IC VREG LDO 1A 3.3V SOT223; AGILE_PN: 312-80039; CAD_APPROVED: Yes; HEIGHT: 1.8MM; MFG_NAME01: ON Semiconductor; ROHS: Yes
U7 = MMA8451Q_16P_A: IC 3-AXIS DIG ACCELEROMETER 14/8BIT 1.95-3.6V QFN16; AGILE_PN: 315-79075; CAD_APPROVED: Yes; HEIGHT: 1MM; MFG_NAME01: FREESCALE SEMICONDUCTOR; MFG_PN01: MMA8451QT; ROHS: Yes

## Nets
GND: BT1.3(neg) C1.2 C2.2 C7.2 C8.2 C9.2 C10.2 C11.2 C12.2 C13.2 C14.2 C15.2 C16.2 C17.2 C18.2 C19.2 C20.2 C22.2 C26.2 C27.2 C28.2 C29.2 C31.2 C32.2 C33.2 C34.2 C35.2 C36.2 D6.1(GND) J2.7 J3.6 J3.7 J7.3(A2) J7.5(A3) J8.3(A2) J8.5(A3) J9.5(GND1) J22.2 L4.2 R9.2 R14.2 R24.2 R39.2 SW1.2(NO) SW2.2(NO) SW3.2(NO) TP20.1(Pin1) TP21.1(Pin1) TP22.1(Pin1) TP23.1(Pin1) U1.4(VSS) U1.25(EXPAD) U2.2(VSS1) U2.8(VSSA) U2.33(EPAD) U4.7(GND) U6.1(GND) U7.5(GND1) U7.10(GND2) U7.12(GND3) Y2.2(GND1) Y2.4(GND2)
P3V3: C17.1 C18.1 C20.1 D3.C D4.2(COMMON_A) D8.C J3.2 J3.4 J5.1 J10.1 R13.1 R21.1 R22.1 R27.1 R28.1 R29.1 R30.1 R32.1 R38.1 R53.2 R54.1 R55.1 U7.1(VDDIO) U7.14(VDD)
P3V3_BATT: BT1.1(pos1) BT1.2(pos2) C14.1 D8.A TP15.1(Pin1)
P3V3_MCU: C1.1 C22.1 J7.1(A1) J10.2 R25.1 R27.2 R32.2 U1.3(VDD)
P3V3_USBSER: C9.1 C36.1 J5.2 J8.1(A1) R4.1 R7.2 R10.1 R15.1 R23.1 R28.2 U2.1(VDD1) U2.7(VDDA) U4.4(~{OE2}) U4.14(VCC)
P3V3_VREG: C16.1 D3.A R53.1 TP16.1(Pin1) U6.2(VOUT) U6.4(TAB)
P5V0-9V0_VIN: C26.1 C27.1 C28.1 D7.A J3.8 J22.1
P5V0_SDA_USB_CONN_VBUS: D6.4(VDD) J9.1(VBUS) L3.1
P5V0_USBSER: C8.1 D2.A D5.A L3.2 R8.1 R12.1 U2.6(VREGIN)
P5V_USB_CONNECTORS: C29.1 D5.C J3.5 J22.3
A5: J4.6 R11.2
ACCEL_INT: R26.2 U7.9(INT2)
ACCEL_SCL: R48.2 U7.4(SCL)
ACCEL_SDA: R49.2 U7.6(SDA)
ADC0_SE0/CMP0_IN0/PTA12/IRQ_13/LPTMR0_ALT2/TPM1_CH0/TPM_CLKIN0: J4.3 R26.1 U1.20(PTA12/IRQ_13/ADC0_SE0/CMP0_IN0/TPM1_CH0/TPM_CLKIN0/CLKOUT/LPTMR0_ALT2)
ADC0_SE1/CMP0_IN1/PTB5/IRQ_12/TPM1_CH1/NMI_b: J1.7 R36.1 U1.19(PTB5/IRQ_12/ADC0_SE1/CMP0_IN1/TPM1_CH1/~{NMI})
ADC0_SE2/PTA9/I2C0_SDA/SPI0_SCK: J4.1 R35.1 U1.16(PTA9/ADC0_SE2/I2C0_SDA/SPI0_SCK)
ADC0_SE3/PTA8/I2C0_SCL/SPI0_MOSI: J4.2 R34.1 U1.15(PTA8/ADC0_SE3/I2C0_SCL/SPI0_MOSI)
ADC0_SE8/CMP0_IN3/PTB1/IRQ_6/UART0_TX/UART0_RX/I2C0_SDA: J1.2 R16.2 U1.13(PTB1/IRQ_6/ADC0_SE8/CMP0_IN3/LPUART0_TX/LPUART0_RX/I2C0_SDA)
ADC0_SE9/PTB0/IRQ_5/LLWU_P4/EXTRG_IN/SPI0_SCK/I2C0_SCL: J2.6 R37.1 U1.12(PTB0/IRQ_5/ADC0_SE9/EXTRG_IN/SPI0_SCK/I2C0_SCL/LLWU_P4)
ADC0_SE15/CMP0_IN2/PTA0/IRQ_0/LLWU_P7/TPM1_CH0/SWD_CLK: J1.8 J6.2 U1.22(PTA0/IRQ_0/ADC0_SE15/CMP0_IN2/TPM1_CH0/SWD_CLK/LLWU_P7)
AREF: J2.8 R25.2
EXTAL: R1.1 U1.5(PTA3/EXTAL0/I2C0_SCL/I2C0_SDA/LPUART0_TX)
LEDRGB_BLUE: D4.3(BLUE_C) R20.1 TP19.1(Pin1)
LEDRGB_GREEN: D4.4(GREEN_C) R19.1 TP18.1(Pin1)
LEDRGB_RED: D4.1(RED_C) R18.2 TP17.1(Pin1)
MMA8451_BYP: C19.1 TP24.1(Pin1) U7.2(BYP)
PTA2/CMP0_OUT/SWD_DIO: J4.4 R52.2
PTA5/RTC_CLKIN/TPM0_CH1/SPI0_SS_b: J2.3 U1.7(PTA5/RTC_CLK_IN/TPM0_CH1/~{SPI0_SS})
PTA6/TPM0_CH0/SPI0_MISO: J2.5 U1.8(PTA6/TPM0_CH0/SPI0_MISO)
PTA7/IRQ_4/SPI0_MISO/SPI0_MOSI: J2.4 U1.11(PTA7/IRQ_4/SPI0_MISO/SPI0_MOSI)
PTB3/IRQ_10/I2C0_SCL/UART0_TX: J2.10 R21.2 R48.1 U1.17(PTB3/IRQ_10/I2C0_SCL/LPUART0_TX)
PTB4/IRQ_11/I2C0_SDA/UART0_RX: J2.9 R22.2 R49.1 U1.18(PTB4/IRQ_11/I2C0_SDA/LPUART0_RX)
PTB6/IRQ_2/LPTMR0_ALT3/TPM1_CH1/TPM_CLKIN1: J1.4 R44.1 U1.1(PTB6/IRQ_2/TPM1_CH1/TPM_CLKIN1/LPTMR0_ALT3)
PTB7/IRQ_3/TPM1_CH0: J1.6 R45.1 U1.2(PTB7/IRQ_3/TPM1_CH0)
PTB10/TPM0_CH1/SPI0_SS_b: J2.1 R18.1 U1.9(PTB10/TPM0_CH1/~{SPI0_SS})
PTB11/TPM0_CH0/SPI0_MISO: J2.2 R19.2 U1.10(PTB11/TPM0_CH0/SPI0_MISO)
PTB13/CLKOUT32K/TPM1_CH1/RTC_CLKOUT: J4.5 R20.2 U1.21(PTB13/CLKOUT32K/TPM1_CH1/RTC_CLKOUT)
RST_TGTMCU: C13.1 J3.3 J7.10(B5) J11.2 R13.2 R31.2 SW1.1(COMMON) U1.23(PTA1/IRQ_1/TPM_CLKIN0/~{RESET}/LPTMR0_ALT1)
SDA_EXTAL: C11.1 U2.17(EXTAL0/PTA18/FTM0_FLT2/FTM_CLKIN0) Y2.3
SDA_JTAG_TCLK: J8.4(B2) U2.12(JTAG_TCLK/SWD_CLK/EZP_CLK/TSI0_CH1/PTA0/~{UART0_CTS}/~{UART0_COL}/FTM0_CH5)
SDA_JTAG_TDI: J8.8(B4) U2.13(JTAG_TDI/EZP_DI/TSI0_CH2/PTA1/UART0_RX/FTM0_CH6)
SDA_JTAG_TDO: J8.6(B3) U2.14(JTAG_TDO/TRACE_SWO/EZP_DO/TSI0_CH3/PTA2/UART0_TX/FTM0_CH7)
SDA_JTAG_TMS: J8.2(B1) R15.2 U2.15(JTAG_TMS/SWD_DIO/TSI0_CH4/PTA3/~{UART0_RTS}/FTM0_CH0)
SDA_LED: D1.C(CATHODE) TP6.1(Pin1) U2.29(PTD4/SPI0_PCS1/~{UART0_RTS}/FTM0_CH4/EWM_IN/LLWU_P14)
SDA_LED_R: D1.A(ANODE) R10.2
SDA_PTD5: J3.1 U2.30(ADC0_SE6B/PTD5/SPI0_PCS2/~{UART0_CTS}/~{UART0_COL}/FTM0_CH5/~{EWM_OUT})
SDA_PTD6: R11.1 U2.31(ADC0_SE7B/PTD6/SPI0_PCS3/UART0_RX/FTM0_CH6/FTM0_FLT0/LLWU_P15)
SDA_RST: J8.10(B5) R8.2 R9.1 TP5.1(Pin1) U2.19(~{RESET})
SDA_RST_TGTMCU: J11.1 R31.1 U2.21(ADC0_SE9/TSI0_CH6/PTB1/I2C0_SDA/FTM1_CH1/FTM1_QD_PHB)
SDA_SPI0_SCK: U2.26(PTC5/SPI0_SCK/LPTMR0_ALT2/I2S0_RXD0/CMP0_OUT/LLWU_P9) U4.12(4A)
SDA_SPI0_SIN: U2.28(CMP0_IN1/PTC7/SPI0_SIN/USB_SOF_OUT/I2S0_RX_FS) U4.8(3Y)
SDA_SPI0_SOUT: U2.27(CMP0_IN0/PTC6/SPI0_SOUT/PDB0_EXTRG/I2S0_RX_BCLK/I2S0_MCLK/LLWU_P10) U4.2(1A)
SDA_SWD_EN: R4.2 U2.16(~{NMI}/~{EZP_CS}/TSI0_CH5/PTA4/FTM0_CH1/LLWU_P3) U4.10(~{OE3}) U4.13(~{OE4})
SDA_SWD_OE_B: R7.1 U2.20(ADC0_SE8/TSI0_CH0/PTB0/I2C0_SCL/FTM1_CH0/FTM1_QD_PHA/LLWU_P5) U4.1(~{OE1})
SDA_USB_CONN_DN: D6.2(I/O1) J9.2(D-) R5.1
SDA_USB_CONN_DP: D6.3(I/O2) J9.3(D+) R6.1
SDA_USB_DN: R5.2 U2.4(USB0_DM)
SDA_USB_DP: R6.2 U2.3(USB0_DP)
SDA_USB_P5V_SENSE: R12.2 R14.1 TP7.1(Pin1) U2.32(PTD7/CMT_IRO/UART0_TX/FTM0_CH7/FTM0_FLT1)
SDA_USB_VOUT33: C12.1 U2.5(VOUT33)
SDA_USBSHIELD: J9.S1(SHLD1) J9.S2(SHLD2) J9.S3(SHLD3) J9.S4(SHLD4) L4.1
SDA_XTAL: C10.1 U2.18(XTAL0/PTA19/FTM1_FLT0/FTM_CLKIN1/LPTMR0_ALT1) Y2.1
SW_LLWU: C33.1 R37.2 R54.2 SW2.1(COMMON)
SW_NMI_b: C34.1 R36.2 R55.2 SW3.1(COMMON)
SWD_CLK_TGTMCU: J6.1 J7.4(B2) U4.11(4Y)
SWD_DIO_TGTMCU: J7.2(B1) R33.2 U4.3(1Y) U4.9(3A)
TC_74125_SPARE_I_TP: TP11.1(Pin1) U4.5(2A)
TC_74125_SPARE_O_TP: TP13.1(Pin1) U4.6(2Y)
TC_EXTAL_TP: TP3.1(Pin1) U2.10(EXTAL32)
TC_SDA_USB_ID_TP: J9.4(ID) TP2.1(Pin1)
TC_VBAT_TP: TP1.1(Pin1) U2.11(VBAT)
TC_XTAL_TP: TP4.1(Pin1) U2.9(XTAL32)
THER_A: C32.1 R34.2 R41.1
THER_B: C31.1 R35.2 R40.1
THER_N: C30.2 R39.1 R40.2 RT1.2
THER_P: C30.1 R38.2 R41.2 RT1.1
TOUCH_A: E1.1 R29.2 R45.2
TOUCH_B: E1.2 R30.2 R44.2
UART0_RX_TGTMCU: R17.1 U2.25(PTC4/SPI0_PCS0/UART1_TX/FTM0_CH3/CMP1_OUT/LLWU_P8)
UART0_TX_TGTMCU: R16.1 U2.24(CMP1_IN1/PTC3/SPI0_PCS1/UART1_RX/FTM0_CH2/I2S0_TX_BCLK/LLWU_P7)
VREF_CAP/CMP_IN5/PTB2/IRQ_7/UART0_RX/UART0_TX: C35.1 J1.1 R17.2 U1.14(PTB2/IRQ_7/VREF_OUT/CMP_IN5/LPUART0_RX/LPUART0_TX)
XTAL: R3.1 U1.6(PTA4/XTAL0/I2C0_SDA/I2C0_SCL/LPUART0_RX/CLKOUT)
N20057318: C15.1 D2.C D7.C U6.3(VIN)
N20181399: R23.2 R24.1 TP25.1(Pin1) U7.7(SA0)
N51885583: C2.1 R1.2 R2.1 Y1.1
N51886520: R33.1 R52.1 U1.24(PTA2/CMP0_OUT/SWD_DIO)
N51910298: C7.1 R2.2 R3.2 Y1.4

Not connected (* = marked no-connect by the designer): J1 3* 5*; J7 6(B3)* 7(A4)* 8(B4)* 9(A5)*; J8 7(A4)* 9(A5)*; U2 22(ADC0_SE15/TSI0_CH14/PTC1/SPI0_PCS3/~{UART1_RTS}/FTM0_CH0/I2S0_TXD0/LLWU_P6)* 23(ADC0_SE4B/CMP1_IN0/TSI0_CH15/PTC2/SPI0_PCS2/~{UART1_CTS}/FTM0_CH1/I2S0_TX_FS)*; U7 3(NC3)* 8(NC8)* 11(INT1)* 13(NC13)* 15(NC15)* 16(NC16)*; Y1 2* 3*

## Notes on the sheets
sheet 1
- Table of Contents
- Revisions
- page 1
- Table and Revision
- Rev
- Description
- Date
- Approved
- page 2
- Notes
- X1
- Initial
- Dec. 9, 2013
- page 3
- MCU
- page 4
- OpenSDA
- A
- Release
- Dec. 19, 2013
- page 5
- Power and Peripherals
- Change pin usage of PTB0, PTB1, PTB2,
  PTB3, PTB4, PTA9
- A1
- Feb. 24, 2014
- B
- DNP J1, J2, J3, J4, J5, J7, J8, J10, J11,
  TP20 and BT1. Populate R27, R28, R31 and R32
- Feb. 26, 2014
- Change C31 & C32 from 2200pF to 220pF
- B1
- Update U1 from PKL03Z16VFK4 to PKL03Z32VFK4
- Mar. 05, 2014
- B2
- Change R16, R17 to 0 ohm
- May 21, 2014
- Aug. 20, 2014
- B3
- Update KL03 pin names
- FREEDOM KL03Z
sheet 3
- There is a bottom-layer trace
  shorting pin 1 to pin 2 of jumper
- SWD CONNECTOR
- D7/SWD_CLK
- D13/LLWU
- RESET
- D1/UART0_TX
- A3/SWD_DIO
- D0/UART0_RX/VREF_CAP
- EXTAL
- D15/ACCEL_I2C_SCL
- XTAL
- D14/ACCEL_I2C_SDA
- D10
- D12
- D3/TOUCH
- D6/SW_NMI
- D11
- D5/TOUCH
- A1/THERMISTOR
- D8/RGB_RED
- A0/THERMISTOR
- D9/RGB_GREEN
- A2/ACCEL_INT
- A4/RGB_BLUE
- PTB3&PTB4 Open Drain
- 90C to -20C
- Vdiff ~ 0.372V to 2.879V
  (Ta=25C 1.650V)
- THERMISTOR
sheet 4
- Use Jumper J11 in prototype for debug
  DNP J11 and populate R31 in production
- TARGET MCU
  INTERFACE
  SIGNALS
- PU/PD LOGIC:
  SERIAL INTERFACE
  IS ALWAYS RESET
  WHEN USB PORT
  IS DISCONNECTED
- Target reset and bootloader mode
  push button
- OPEN-SDA INTERFACE
- SPARE 74HC125 buffer
- OPEN-SDA INTERFACE JTAG CONNECTOR
sheet 5
- OPTIONAL
  COIN CELL
  HOLDER
- Use Jumper J10, J5 in prototype for debug
  DNP J10 & J5 and populate R32, R27 and R28 in production
- RGB LED FEATURE
- 20mOhm Resistor in layout
- DEBUG GROUND HOOK
- IN CIRCUIT TEST
  GND PROBING
- I2C INERTIAL SENSOR
- 5VDC VR
  SUPPORT
- IN
- OUT
- ARDUINO UNO
- COMPATIBLE SHIELDS
- TOUCH ELECTRODES
